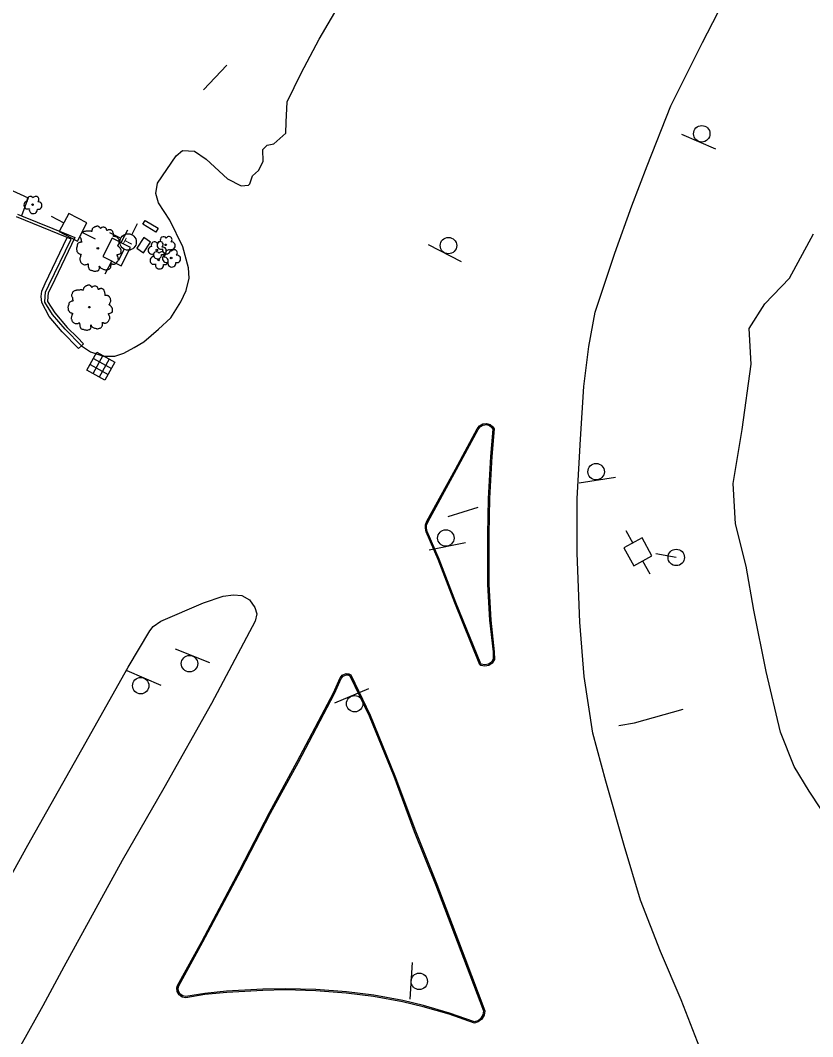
# Model space of a CAD drawing. Extents: x 2161152 to 2175754, y 602179 to 617749.
# Drawn here: x 2173771.8 to 2173964.4, y 616255.2 to 616502.3 of the extents above; entities that cross this region are included whole.
import ezdxf

# ---------------------------------------------------------------- set-up
doc = ezdxf.new("R2010")
doc.units = 0
for name, color, linetype in [('RD_EX_BldgApp_Sign', 7, 'Continuous'), ('RD_EX_Conc_Curb', 7, 'Continuous'), ('RD_EX_Conc_Gutter', 7, 'Continuous'), ('RD_EX_Conc_Slab', 7, 'Continuous'), ('RD_EX_DR_Inlet', 7, 'Continuous'), ('RD_EX_Driveway_Asphalt', 7, 'Continuous'), ('RD_EX_Parking_Asphalt', 7, 'Continuous'), ('RD_EX_Road', 7, 'Continuous'), ('RD_EX_UT', 7, 'Continuous'), ('RD_EX_VEG', 7, 'Continuous')]:
    doc.layers.add(name, color=color, linetype=linetype)

msp = doc.modelspace()

# ---------------------------------------------------------------- linework, layer by layer
at = {"layer": 'RD_EX_BldgApp_Sign'}
for p, q in [((2173816.33, 616485.37), (2173822.04, 616491.43)), ((2173932.53, 616474.65), (2173940.79, 616471.08)), ((2173870.94, 616447.78), (2173878.96, 616443.69)), ((2173907.63, 616389.88), (2173916.53, 616391.23)), ((2173875.79, 616381.69), (2173883.11, 616383.97)), ((2173871.23, 616373.55), (2173880.05, 616375.33)), ((2173817.88, 616346.11), (2173809.51, 616349.44)), ((2173806.02, 616340.62), (2173797.75, 616344.17)), ((2173856.46, 616339.78), (2173848.18, 616336.25)), ((2173867.05, 616273.28), (2173866.49, 616264.3))]:
    msp.add_line(p, q, dxfattribs=at)
for points in [[(2173804.77, 616450.83), (2173801.6, 616452.75), (2173802.15, 616453.66), (2173805.28, 616451.77), (2173804.77, 616450.83)], [(2173917.29, 616330.83), (2173921.1, 616331.48), (2173932.97, 616334.8)]]:
    msp.add_lwpolyline(points, dxfattribs=at)
for centre in [(2173937.48, 616474.71), (2173875.89, 616447.53), (2173911.79, 616392.56), (2173875.25, 616376.43), (2173812.93, 616345.9), (2173801.07, 616340.54), (2173853.09, 616336.15), (2173868.79, 616268.65)]:
    msp.add_circle(centre, 2, dxfattribs=at)
at = {"layer": 'RD_EX_Conc_Curb'}
for points in [[(2173771.12, 616455.14), (2173772.1, 616454.75), (2173783.47, 616450.11), (2173785.02, 616449.48), (2173779.34, 616437.62), (2173778.59, 616436.03), (2173778.47, 616435.12), (2173778.4, 616433.93), (2173780.15, 616431.15), (2173783.18, 616427.65), (2173785.66, 616425.15), (2173787.17, 616423.65), (2173786.81, 616423.29), (2173786.7, 616423.18), (2173782.69, 616427.19), (2173779.6, 616430.77), (2173777.75, 616433.75), (2173777.8, 616435.13), (2173777.94, 616436.21), (2173778.73, 616437.9), (2173784.16, 616449.11), (2173783.22, 616449.5), (2173770.88, 616454.52)], [(2173883.5, 616345.6), (2173877.44, 616360.66), (2173873.37, 616371.21), (2173870.44, 616377.94), (2173870.27, 616378.84), (2173870.29, 616379.66), (2173870.67, 616380.57), (2173877.59, 616393.21), (2173882.86, 616402.95), (2173883.41, 616403.71), (2173884.21, 616404.19), (2173885.15, 616404.3), (2173886.04, 616404.02), (2173886.7, 616403.47), (2173887.01, 616402.97), (2173886.45, 616396.23), (2173885.85, 616386.03), (2173885.71, 616377.32), (2173885.68, 616365.11), (2173886.17, 616356.45), (2173887.04, 616348.77), (2173887.11, 616346.87), (2173886.55, 616346.04), (2173885.72, 616345.48), (2173884.75, 616345.28), (2173883.77, 616345.47), (2173883.5, 616345.6)], [(2173883.73, 616345.82), (2173877.72, 616360.77), (2173873.64, 616371.33), (2173870.73, 616378.03), (2173870.57, 616378.86), (2173870.59, 616379.6), (2173870.94, 616380.44), (2173877.85, 616393.07), (2173883.12, 616402.79), (2173883.61, 616403.49), (2173884.31, 616403.9), (2173885.12, 616404), (2173885.9, 616403.76), (2173886.47, 616403.27), (2173886.71, 616402.9), (2173886.15, 616396.25), (2173885.56, 616386.04), (2173885.41, 616377.32), (2173885.38, 616365.11), (2173885.87, 616356.43), (2173886.74, 616348.75), (2173886.8, 616346.96), (2173886.34, 616346.26), (2173885.61, 616345.76), (2173884.75, 616345.59), (2173883.86, 616345.76), (2173883.73, 616345.82)], [(2173882.24, 616258.47), (2173876.06, 616260.67), (2173869.76, 616262.5), (2173864.7, 616263.68), (2173857.69, 616264.96), (2173851.05, 616265.81), (2173843.61, 616266.38), (2173836.16, 616266.56), (2173830.79, 616266.44), (2173821.98, 616265.94), (2173816.68, 616265.44), (2173812.05, 616264.64), (2173811.15, 616264.82), (2173810.41, 616265.35), (2173809.95, 616266.15), (2173809.87, 616267.06), (2173810.04, 616267.67), (2173815.94, 616278.38), (2173825.15, 616295.74), (2173832.39, 616309.68), (2173839.13, 616322.13), (2173847.9, 616338.77), (2173849.56, 616342.43), (2173850.07, 616343.08), (2173851.06, 616343.48), (2173851.67, 616343.45), (2173852.14, 616343.19), (2173856.88, 616333.33), (2173862.86, 616318.65), (2173867.84, 616305.23), (2173873.03, 616292.3), (2173879.86, 616274.38), (2173884.72, 616261.5), (2173884.54, 616260.43), (2173883.99, 616259.49), (2173883.15, 616258.8), (2173882.24, 616258.47)], [(2173882.24, 616258.79), (2173876.15, 616260.96), (2173869.84, 616262.79), (2173864.76, 616263.97), (2173857.73, 616265.26), (2173851.08, 616266.11), (2173843.63, 616266.68), (2173836.16, 616266.86), (2173830.78, 616266.74), (2173821.96, 616266.24), (2173816.64, 616265.74), (2173812.05, 616264.94), (2173811.27, 616265.1), (2173810.64, 616265.56), (2173810.25, 616266.24), (2173810.17, 616267.03), (2173810.32, 616267.55), (2173816.21, 616278.24), (2173825.42, 616295.6), (2173832.66, 616309.54), (2173839.4, 616321.98), (2173848.17, 616338.64), (2173849.81, 616342.27), (2173850.25, 616342.83), (2173851.12, 616343.18), (2173851.59, 616343.15), (2173851.92, 616342.97), (2173856.61, 616333.21), (2173862.59, 616318.54), (2173867.56, 616305.12), (2173872.75, 616292.19), (2173879.58, 616274.28), (2173884.41, 616261.47), (2173884.25, 616260.53), (2173883.76, 616259.68), (2173883, 616259.06), (2173882.24, 616258.79)]]:
    msp.add_lwpolyline(points, dxfattribs=at)
at = {"layer": 'RD_EX_Conc_Gutter'}
msp.add_lwpolyline([(2173786.7, 616423.18), (2173785.98, 616422.48), (2173782, 616426.53), (2173778.83, 616430.27), (2173777.01, 616433.68), (2173776.88, 616435.17), (2173777.05, 616436.48), (2173777.82, 616438.31), (2173783.22, 616449.5)], dxfattribs=at)
at = {"layer": 'RD_EX_Conc_Slab'}
msp.add_lwpolyline([(2173755.6, 616462.38), (2173757.49, 616466.48), (2173773.72, 616459.1), (2173772.1, 616454.75)], dxfattribs=at)
at = {"layer": 'RD_EX_DR_Inlet'}
for p, q in [((2173791.87, 616420.77), (2173789.45, 616416.39)), ((2173788.74, 616418.61), (2173793.12, 616416.19)), ((2173789.56, 616420.1), (2173793.94, 616417.68)), ((2173793.36, 616419.94), (2173790.94, 616415.57))]:
    msp.add_line(p, q, dxfattribs=at)
msp.add_lwpolyline([(2173787.97, 616417.21), (2173790.39, 616421.59), (2173794.76, 616419.17), (2173792.34, 616414.79)], close=True, dxfattribs=at)
at = {"layer": 'RD_EX_Driveway_Asphalt'}
msp.add_lwpolyline([(2173812.69, 616442.09), (2173811.31, 616447.2), (2173808.18, 616453.74), (2173805.39, 616457.89), (2173804.72, 616460.22), (2173805.18, 616462.71), (2173809.7, 616469.32), (2173811.25, 616470.66), (2173814.14, 616470.45), (2173816.99, 616468.53), (2173822.15, 616463.79), (2173825.5, 616462.09)], dxfattribs=at)
at = {"layer": 'RD_EX_Parking_Asphalt'}
msp.add_lwpolyline([(2173786.7, 616423.18), (2173788.83, 616421.74), (2173792.04, 616420.67), (2173794.74, 616420.66), (2173797, 616421.4), (2173799.47, 616422.72), (2173801.82, 616424.17), (2173805.39, 616427.18), (2173808.36, 616430), (2173810.83, 616433.89), (2173812.09, 616436.63), (2173812.83, 616439.64), (2173812.69, 616442.09)], dxfattribs=at)
at = {"layer": 'RD_EX_Road'}
for points in [[(2173937.57, 616251.01), (2173932.47, 616264.16), (2173927.46, 616275.92), (2173922.57, 616288.37), (2173918.63, 616301.72), (2173914.15, 616317.33), (2173910.96, 616329.01), (2173908.91, 616342.81), (2173907.83, 616355.98), (2173907.17, 616372.78), (2173907.15, 616386.06), (2173907.98, 616400.47), (2173908.77, 616413.31), (2173910.01, 616422.96), (2173911.54, 616431.36), (2173916.33, 616445.67), (2173920.45, 616457.17), (2173924.19, 616466.9), (2173929.97, 616481.51), (2173937.62, 616496.87), (2173947.61, 616516.26), (2173962.82, 616543.95), (2173976.96, 616568.18)], [(2173825.5, 616462.09), (2173827.28, 616462.24), (2173827.62, 616462.56), (2173828.26, 616464.46), (2173829.68, 616465.81), (2173830.86, 616467.95), (2173830.74, 616470.92), (2173831.82, 616471.95), (2173833.47, 616472.24), (2173836.38, 616474.86), (2173836.44, 616477.5), (2173836.64, 616482.44), (2173840.04, 616489.41), (2173844.48, 616497.73), (2173857.85, 616520.59)], [(2173752.35, 616254.46), (2173750.76, 616257.96), (2173750.44, 616259.84), (2173761.32, 616279.55), (2173773.65, 616301.79), (2173786.76, 616325.03), (2173798.04, 616345.07), (2173803.28, 616353.89), (2173804.13, 616354.96), (2173805.97, 616356.26), (2173816.33, 616360.71), (2173821.12, 616362.3), (2173823.63, 616362.63), (2173825.63, 616362.48), (2173827.55, 616361.41), (2173828.79, 616359.56), (2173829.27, 616357.97), (2173828.93, 616356.23), (2173818.27, 616336.22), (2173806.71, 616315.66), (2173796.58, 616298.07), (2173782.35, 616272.16), (2173777.23, 616262.74), (2173771.81, 616252.97)]]:
    msp.add_lwpolyline(points, dxfattribs=at)
at = {"layer": 'RD_EX_UT'}
for p, q in [((2173783.56, 616455.37), (2173781.25, 616450.93)), ((2173788, 616453.06), (2173783.56, 616455.37)), ((2173779.33, 616454.67), (2173782.41, 616453.07)), ((2173785.69, 616448.62), (2173788, 616453.06)), ((2173798.9, 616450.17), (2173800.31, 616452.9)), ((2173781.25, 616450.93), (2173785.69, 616448.62)), ((2173786.75, 616450.82), (2173789.98, 616449.14)), ((2173793.49, 616450.71), (2173796.22, 616449.3)), ((2173797.85, 616451.27), (2173796.27, 616448.18)), ((2173794.12, 616449.33), (2173791.84, 616444.88)), ((2173798.57, 616447.05), (2173794.12, 616449.33)), ((2173795.73, 616444.01), (2173797.07, 616446.62)), ((2173796.29, 616442.6), (2173798.57, 616447.05)), ((2173791.84, 616444.88), (2173796.29, 616442.6)), ((2173794.04, 616443.83), (2173792.38, 616440.59)), ((2173922.95, 616376.48), (2173918.56, 616374.08)), ((2173919.05, 616378.26), (2173920.72, 616375.22)), ((2173925.35, 616372.1), (2173922.95, 616376.48)), ((2173918.56, 616374.08), (2173920.97, 616369.7)), ((2173920.97, 616369.7), (2173925.35, 616372.1)), ((2173923.07, 616370.93), (2173924.82, 616367.74)), ((2173931.27, 616371.72), (2173926.35, 616372.61))]:
    msp.add_line(p, q, dxfattribs=at)
msp.add_lwpolyline([(2173800.12, 616446.88), (2173801.77, 616445.79), (2173803.48, 616448.38), (2173801.84, 616449.47), (2173800.12, 616446.88)], dxfattribs=at)
for centre in [(2173798, 616448.39), (2173931.27, 616371.72)]:
    msp.add_circle(centre, 2, dxfattribs=at)
at = {"layer": 'RD_EX_VEG'}
msp.add_lwpolyline([(2173969.41, 616306.06), (2173963.62, 616314.92), (2173959.94, 616320.91), (2173956.64, 616329.26), (2173953.1, 616343.97), (2173950.11, 616358.91), (2173948.24, 616369.58), (2173945.68, 616379.88), (2173945.09, 616389.69), (2173947.3, 616402.81), (2173949.51, 616418.71), (2173948.99, 616427.34), (2173952.85, 616433.37), (2173958.83, 616439.57), (2173964.63, 616450.41)], dxfattribs=at)
for centre, radius in [((2173774.77, 616457.48), 0.188), ((2173807.16, 616447.71), 0.188), ((2173790.64, 616446.86), 0.188), ((2173790.64, 616446.85), 0.000075), ((2173804.99, 616446.48), 0.188), ((2173805.45, 616444.03), 0.188), ((2173808.46, 616444.51), 0.188), ((2173788.56, 616432.55), 0.188), ((2173788.55, 616432.53), 0.000075)]:
    msp.add_circle(centre, radius, dxfattribs=at)
for centre, radius, start, end in [((2173773.6, 616457.36), 0.943, 96.4518, 294.734), ((2173774.23, 616458.64), 0.813, 34.9763, 204.756), ((2173775.56, 616458.76), 0.746, 308.7626, 152.0467), ((2173776.15, 616457.27), 0.914, 256.5667, 98.1046), ((2173774.96, 616456.28), 0.988, 166.8827, 5.7589), ((2173804.44, 616447.64), 0.813, 34.9763, 204.756), ((2173805.99, 616447.59), 0.943, 96.4518, 294.734), ((2173805.77, 616447.75), 0.746, 308.7626, 152.0467), ((2173806.62, 616448.87), 0.813, 34.9763, 204.756), ((2173807.94, 616448.98), 0.746, 308.7626, 152.0467), ((2173808.54, 616447.5), 0.914, 256.5667, 98.1046), ((2173803.81, 616446.36), 0.943, 96.4518, 294.734), ((2173804.91, 616445.19), 0.813, 34.9763, 204.756), ((2173805.17, 616445.28), 0.988, 166.8827, 5.7589), ((2173806.23, 616445.3), 0.746, 308.7626, 152.0467), ((2173806.36, 616446.27), 0.914, 256.5667, 98.1046), ((2173807.29, 616444.39), 0.943, 96.4518, 294.734), ((2173807.34, 616446.51), 0.988, 166.8827, 5.7589), ((2173807.92, 616445.67), 0.813, 34.9763, 204.756), ((2173809.24, 616445.79), 0.746, 308.7626, 152.0467), ((2173809.84, 616444.3), 0.914, 256.5667, 98.1046), ((2173804.28, 616443.91), 0.943, 96.4518, 294.734), ((2173805.63, 616442.83), 0.988, 166.8827, 5.7589), ((2173806.83, 616443.82), 0.914, 256.5667, 98.1046), ((2173808.64, 616443.31), 0.988, 166.8827, 5.7589)]:
    msp.add_arc(centre, radius, start, end, dxfattribs=at)
for points in [[(2173790.74, 616452.24), (2173790.52, 616452.25), (2173790.28, 616452.18), (2173790.09, 616452.1), (2173789.92, 616452.05), (2173789.75, 616451.97), (2173789.53, 616451.84), (2173789.36, 616451.69), (2173789.26, 616451.5), (2173789.23, 616451.34), (2173789.19, 616451.13), (2173789.19, 616451), (2173789.09, 616450.98), (2173788.98, 616451), (2173788.79, 616451.05), (2173788.61, 616451.05), (2173788.42, 616451.05), (2173788.16, 616451.04), (2173787.89, 616451.04), (2173787.69, 616451), (2173787.44, 616450.96), (2173787.16, 616450.87), (2173786.9, 616450.77), (2173786.68, 616450.59), (2173786.49, 616450.23), (2173786.4, 616449.97), (2173786.28, 616449.78), (2173786.4, 616449.44), (2173786.53, 616449.18), (2173786.55, 616449.03), (2173786.6, 616448.71), (2173786.68, 616448.54), (2173786.77, 616448.39), (2173786.71, 616448.37), (2173786.43, 616448.34), (2173786.21, 616448.26), (2173785.89, 616448.09), (2173785.72, 616447.92), (2173785.65, 616447.68), (2173785.63, 616447.42), (2173785.55, 616447.27), (2173785.5, 616447.06), (2173785.48, 616447.01), (2173785.44, 616446.76), (2173785.51, 616446.43), (2173785.53, 616446.16), (2173785.63, 616445.99), (2173785.74, 616445.86), (2173785.87, 616445.68), (2173786.17, 616445.51), (2173786.41, 616445.43), (2173786.56, 616445.41), (2173786.43, 616445.04), (2173786.4, 616444.78), (2173786.3, 616444.48), (2173786.3, 616444.42), (2173786.26, 616444.06), (2173786.38, 616443.82), (2173786.43, 616443.54), (2173786.56, 616443.37), (2173786.77, 616443.15), (2173787.01, 616442.98), (2173787.39, 616442.88), (2173787.69, 616442.9), (2173788.12, 616443.03), (2173788.31, 616443.09), (2173788.29, 616442.96), (2173788.31, 616442.68), (2173788.31, 616442.36), (2173788.42, 616442.11), (2173788.49, 616441.91), (2173788.61, 616441.72), (2173788.85, 616441.55), (2173789.15, 616441.5), (2173789.47, 616441.38), (2173789.81, 616441.33), (2173790.18, 616441.31), (2173790.63, 616441.42), (2173790.84, 616441.51), (2173790.91, 616441.65), (2173791.06, 616441.93), (2173791.02, 616442.1), (2173791.04, 616442.55), (2173791.12, 616442.41), (2173791.25, 616442.15), (2173791.62, 616441.93), (2173791.92, 616441.8), (2173792.28, 616441.68), (2173792.51, 616441.63), (2173792.86, 616441.68), (2173793.14, 616441.74), (2173793.42, 616441.83), (2173793.65, 616442.04), (2173793.78, 616442.25), (2173793.82, 616442.45), (2173793.87, 616442.73), (2173793.91, 616442.86)], [(2173793.91, 616442.86), (2173793.85, 616443), (2173793.82, 616443.18), (2173793.87, 616443.16), (2173794, 616443.13), (2173794.21, 616443.03), (2173794.38, 616442.98), (2173794.62, 616443), (2173794.83, 616443.07), (2173795.17, 616443.28), (2173795.37, 616443.63), (2173795.58, 616443.93), (2173795.64, 616444.18), (2173795.6, 616444.34), (2173795.58, 616444.72), (2173795.43, 616444.91), (2173795.39, 616445), (2173795.32, 616445.3), (2173795.37, 616445.34), (2173795.58, 616445.38), (2173795.86, 616445.47), (2173796.07, 616445.56), (2173796.23, 616445.69), (2173796.29, 616445.86), (2173796.27, 616446.16), (2173796.31, 616446.46), (2173796.25, 616446.58), (2173796.18, 616446.69), (2173796.12, 616446.84), (2173796.01, 616446.95), (2173795.94, 616447.06), (2173795.86, 616447.14), (2173795.77, 616447.25), (2173795.64, 616447.34), (2173795.52, 616447.38), (2173795.49, 616447.49), (2173795.6, 616447.64), (2173795.64, 616447.72), (2173795.65, 616447.89), (2173795.82, 616448.15), (2173795.86, 616448.45), (2173795.82, 616448.77), (2173795.79, 616448.97), (2173795.67, 616449.18), (2173795.52, 616449.37), (2173795.43, 616449.5), (2173795.3, 616449.59), (2173795.05, 616449.69), (2173794.87, 616449.72), (2173794.6, 616449.72), (2173794.45, 616449.76), (2173794.47, 616449.8), (2173794.47, 616449.91), (2173794.47, 616450.12), (2173794.42, 616450.45), (2173794.3, 616450.83), (2173794.3, 616450.85), (2173794.23, 616451.04), (2173794.06, 616451.19), (2173793.93, 616451.26), (2173793.78, 616451.35), (2173793.59, 616451.37), (2173793.37, 616451.37), (2173793.16, 616451.34), (2173793.01, 616451.26), (2173792.88, 616451.17), (2173792.82, 616451.28), (2173792.75, 616451.5), (2173792.71, 616451.62), (2173792.6, 616451.75), (2173792.43, 616451.9), (2173792.09, 616451.99), (2173791.62, 616451.94), (2173791.4, 616451.79), (2173791.29, 616451.65), (2173791.25, 616451.75), (2173791.1, 616451.9), (2173791.02, 616452.03), (2173790.89, 616452.12), (2173790.78, 616452.2), (2173790.71, 616452.24)], [(2173788.66, 616437.92), (2173788.44, 616437.94), (2173788.19, 616437.87), (2173788.01, 616437.79), (2173787.84, 616437.74), (2173787.67, 616437.66), (2173787.44, 616437.53), (2173787.28, 616437.38), (2173787.18, 616437.19), (2173787.14, 616437.02), (2173787.11, 616436.82), (2173787.11, 616436.69), (2173787.01, 616436.67), (2173786.9, 616436.69), (2173786.71, 616436.74), (2173786.53, 616436.74), (2173786.34, 616436.74), (2173786.08, 616436.72), (2173785.81, 616436.72), (2173785.61, 616436.69), (2173785.36, 616436.65), (2173785.08, 616436.55), (2173784.82, 616436.46), (2173784.6, 616436.27), (2173784.41, 616435.92), (2173784.31, 616435.65), (2173784.2, 616435.47), (2173784.31, 616435.13), (2173784.45, 616434.87), (2173784.46, 616434.72), (2173784.52, 616434.4), (2173784.6, 616434.23), (2173784.69, 616434.08), (2173784.63, 616434.06), (2173784.35, 616434.02), (2173784.13, 616433.95), (2173783.81, 616433.78), (2173783.64, 616433.61), (2173783.57, 616433.37), (2173783.55, 616433.11), (2173783.47, 616432.96), (2173783.42, 616432.75), (2173783.4, 616432.69), (2173783.36, 616432.45), (2173783.43, 616432.11), (2173783.45, 616431.85), (2173783.55, 616431.68), (2173783.66, 616431.55), (2173783.79, 616431.36), (2173784.09, 616431.19), (2173784.33, 616431.12), (2173784.48, 616431.1), (2173784.35, 616430.73), (2173784.31, 616430.46), (2173784.22, 616430.16), (2173784.22, 616430.11), (2173784.18, 616429.75), (2173784.3, 616429.51), (2173784.35, 616429.23), (2173784.48, 616429.06), (2173784.69, 616428.83), (2173784.93, 616428.66), (2173785.31, 616428.57), (2173785.61, 616428.59), (2173786.04, 616428.72), (2173786.23, 616428.78), (2173786.21, 616428.65), (2173786.23, 616428.36), (2173786.23, 616428.05), (2173786.34, 616427.8), (2173786.41, 616427.6), (2173786.53, 616427.41), (2173786.77, 616427.24), (2173787.07, 616427.18), (2173787.39, 616427.07), (2173787.73, 616427.01), (2173788.1, 616427), (2173788.55, 616427.11), (2173788.76, 616427.2), (2173788.83, 616427.33), (2173788.98, 616427.61), (2173788.94, 616427.78), (2173788.96, 616428.23), (2173789.04, 616428.1), (2173789.17, 616427.84), (2173789.54, 616427.61), (2173789.84, 616427.48), (2173790.2, 616427.37), (2173790.42, 616427.31), (2173790.78, 616427.37), (2173791.06, 616427.43), (2173791.34, 616427.52), (2173791.57, 616427.73), (2173791.7, 616427.93), (2173791.74, 616428.14), (2173791.79, 616428.42), (2173791.83, 616428.55)], [(2173791.83, 616428.55), (2173791.77, 616428.68), (2173791.74, 616428.87), (2173791.79, 616428.85), (2173791.92, 616428.81), (2173792.13, 616428.72), (2173792.3, 616428.66), (2173792.54, 616428.68), (2173792.75, 616428.76), (2173793.09, 616428.96), (2173793.29, 616429.32), (2173793.5, 616429.62), (2173793.55, 616429.86), (2173793.52, 616430.03), (2173793.5, 616430.41), (2173793.35, 616430.59), (2173793.31, 616430.69), (2173793.24, 616430.99), (2173793.29, 616431.03), (2173793.5, 616431.06), (2173793.78, 616431.16), (2173793.99, 616431.25), (2173794.15, 616431.38), (2173794.21, 616431.55), (2173794.19, 616431.85), (2173794.23, 616432.15), (2173794.17, 616432.26), (2173794.1, 616432.38), (2173794.04, 616432.53), (2173793.93, 616432.64), (2173793.85, 616432.75), (2173793.78, 616432.82), (2173793.69, 616432.94), (2173793.55, 616433.03), (2173793.44, 616433.07), (2173793.4, 616433.18), (2173793.52, 616433.33), (2173793.55, 616433.41), (2173793.57, 616433.57), (2173793.74, 616433.84), (2173793.78, 616434.14), (2173793.74, 616434.46), (2173793.7, 616434.66), (2173793.59, 616434.87), (2173793.44, 616435.06), (2173793.35, 616435.19), (2173793.22, 616435.28), (2173792.97, 616435.37), (2173792.79, 616435.41), (2173792.52, 616435.41), (2173792.37, 616435.45), (2173792.39, 616435.49), (2173792.39, 616435.6), (2173792.39, 616435.8), (2173792.34, 616436.14), (2173792.22, 616436.52), (2173792.22, 616436.54), (2173792.15, 616436.72), (2173791.98, 616436.87), (2173791.85, 616436.95), (2173791.7, 616437.04), (2173791.51, 616437.06), (2173791.29, 616437.06), (2173791.08, 616437.02), (2173790.93, 616436.95), (2173790.8, 616436.85), (2173790.74, 616436.97), (2173790.67, 616437.19), (2173790.63, 616437.3), (2173790.52, 616437.44), (2173790.35, 616437.59), (2173790.01, 616437.68), (2173789.54, 616437.62), (2173789.32, 616437.47), (2173789.21, 616437.34), (2173789.17, 616437.44), (2173789.02, 616437.59), (2173788.94, 616437.72), (2173788.81, 616437.81), (2173788.7, 616437.89), (2173788.63, 616437.92)]]:
    msp.add_spline(points, degree=3, dxfattribs=at)

# ---------------------------------------------------------------- texts
at = {"layer": 'RD_EX_UT'}
msp.add_text('T', height=2, rotation=62.7611, dxfattribs=at).set_placement((2173798.54, 616447.15))

doc.saveas('drawing.dxf')
